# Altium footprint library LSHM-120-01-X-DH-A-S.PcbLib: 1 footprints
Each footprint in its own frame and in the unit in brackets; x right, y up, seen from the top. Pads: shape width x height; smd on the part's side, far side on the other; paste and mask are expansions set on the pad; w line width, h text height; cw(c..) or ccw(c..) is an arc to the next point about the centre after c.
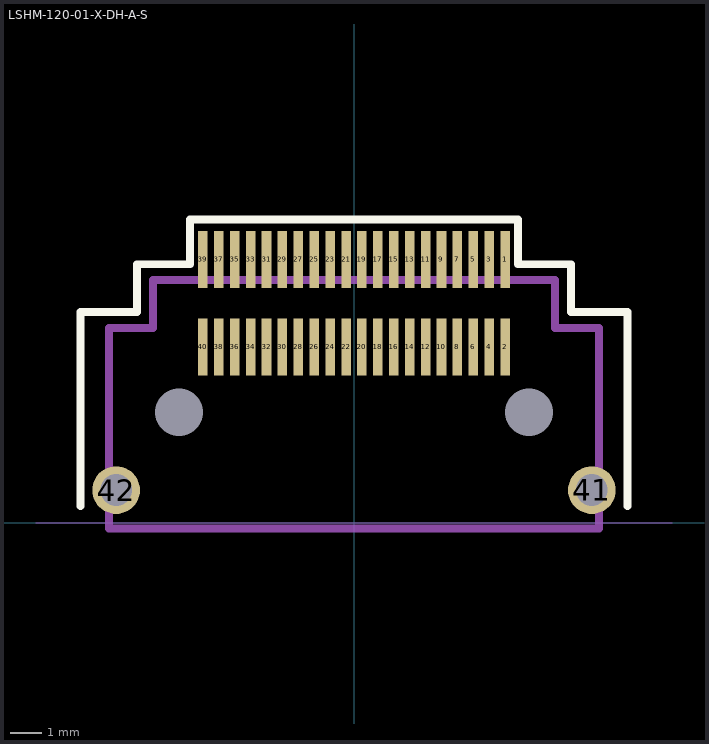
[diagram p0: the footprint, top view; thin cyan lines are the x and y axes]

## LSHM-120-01-X-DH-A-S [mm]
pads (44):
  rect 0.3x1.8 smd mask+0.05: 1(4.75,8.27) 2(4.75,5.52) 3(4.25,8.27) 4(4.25,5.52) 5(3.75,8.27) 6(3.75,5.52) 7(3.25,8.27) 8(3.25,5.52) 9(2.75,8.27) 10(2.75,5.52) 11(2.25,8.27) 12(2.25,5.52) 13(1.75,8.27) 14(1.75,5.52) 15(1.25,8.27) 16(1.25,5.52) 17(0.75,8.27) 18(0.75,5.52) 19(0.25,8.27) 20(0.25,5.52) 21(-0.25,8.27) 22(-0.25,5.52) 23(-0.75,8.27) 24(-0.75,5.52) 25(-1.25,8.27) 26(-1.25,5.52) 27(-1.75,8.27) 28(-1.75,5.52) 29(-2.25,8.27) 30(-2.25,5.52) 31(-2.75,8.27) 32(-2.75,5.52) 33(-3.25,8.27) 34(-3.25,5.52) 35(-3.75,8.27) 36(-3.75,5.52) 37(-4.25,8.27) 38(-4.25,5.52) 39(-4.75,8.27) 40(-4.75,5.52)
  round 1.5 hole 1 mask+0.075: 41(7.475,1.02) 42(-7.475,1.02)
  round 0 hole 1.5 unplated: 43(5.5,3.47) 44(-5.5,3.47)
Top Overlay:
  lines w0.25: -8.6,0.52 -8.6,6.62 -6.815,6.62 -6.815,8.12 -5.154,8.12 -5.154,9.52 5.154,9.52 5.154,8.12 6.815,8.12 6.815,6.62 8.6,6.62 8.6,0.52
Mechanical 1:
  lines w0.25: -7.7,-0.18 -7.7,6.12 -6.315,6.12 -6.315,7.62 6.315,7.62 6.315,6.12 7.7,6.12 7.7,-0.18 -7.7,-0.18
  text "J1" at -0.439,2.07 h0.75
Mechanical 16:
  lines w0.01: -10,0 10,0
